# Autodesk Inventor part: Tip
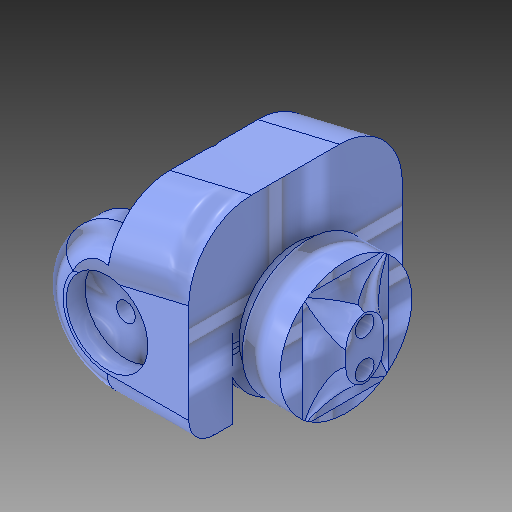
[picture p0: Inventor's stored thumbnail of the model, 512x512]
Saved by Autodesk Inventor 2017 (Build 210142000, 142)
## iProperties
Created: 2017-02
Part Number: Tip
Material: Generic
Document SubType Name: Modeling
Designer: alez_
Density: 1 g/cm^3
Appearance: 4in Square - Light Blue
Author: alez_
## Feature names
1. Extrusion1
2. Extrusion2
3. Extrusion3
4. Extrusion4
5. Extrusion5
6. Extrusion6
7. Extrusion7
8. Extrusion8
9. Sweep1
10. Sweep2
11. Fillet1
12. Fillet2
13. Extrusion9
14. Extrusion10
15. Extrusion11
16. Extrusion12
17. Extrusion13
18. Fillet3
19. Fillet4
20. Extrusion14
21. Extrusion16
22. Extrusion17
23. Extrusion18
24. Fillet5
25. Fillet6
26. Extrusion21
27. Extrusion22
28. Extrusion23
## Parameters: d0 = 18 mm, d1 = 17 mm, d2 = 16 mm, d3 = 0, d4 = 8.5 mm, d6 = 4.25 mm, d7 = 8.5 mm, d8 = 4 mm, d9 = 0, d17 = 17 mm, d18 = 0, d19 = 13.5 mm, d20 = 17 mm, d21 = 0, d22 = 6.5 mm, d23 = 1.5 mm, d24 = 0, d25 = 1.5 mm, d26 = 0, d27 = 1.5 mm, d28 = 14 mm, d29 = 0, d30 = 5 mm, d33 = 8 mm, d34 = 0, d35 = 1.5 mm, d36 = 0, d37 = 0, d38 = 1.5 mm, d39 = 0, d40 = 0, d41 = 5 mm, d42 = 5 mm, d44 = 0, d45 = 11 mm, d47 = 0, d49 = 1 mm, d50 = 1 mm, d51 = 0.75 mm, d52 = 11 mm, d55 = 0, d56 = 10.5 mm, d57 = 1 mm, d58 = 0, d59 = 2 mm, d60 = 0, d61 = 1 mm, d62 = 2 mm, d63 = 15 mm, d64 = 3.25 mm, d65 = 0, d76 = 4 mm, d77 = 0, d78 = -3 mm, d79 = 9 mm, d80 = 1 mm, d81 = 0, d82 = 1.5 mm, d83 = 2.5 mm, d84 = 3 mm, d85 = 5 mm, d86 = 1.5 mm, d87 = 0, d88 = 2 mm, d89 = 2 mm, d105 = 150 deg, d106 = 1.5 mm, d107 = 1.5 mm, d109 = 4.5 mm, d110 = 0, d111 = 0, d112 = 1.5 mm, d113 = 3 mm, d114 = 0, d115 = 1.5 mm, d116 = 1.5 mm, d117 = 5.75 mm, d118 = 0
